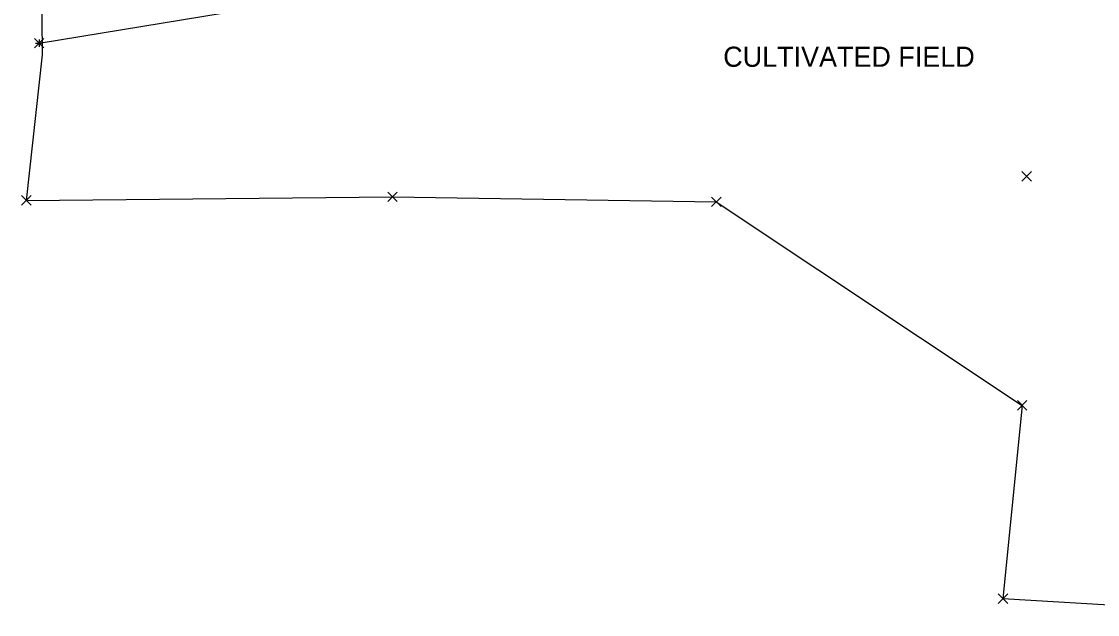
# Model space of a CAD drawing. Extents: x 211013 to 211654, y 505587 to 505872.
# Drawn here: x 211012.8 to 211162.3, y 505603.9 to 505686.3 of the extents above; entities that cross this region are included whole.
import ezdxf

# ---------------------------------------------------------------- set-up
doc = ezdxf.new("R2010")
doc.units = 0
for name, color, linetype in [('DV_X_Section_VMS_Line', 7, 'Continuous'), ('GE_X_Alignment', 7, 'Continuous'), ('RW_X_Esmt_SH', 7, 'Continuous'), ('SV_X_Terrain_Boundary', 7, 'Continuous'), ('SV_X_Text', 7, 'Continuous')]:
    doc.layers.add(name, color=color, linetype=linetype)

msp = doc.modelspace()

# ---------------------------------------------------------------- linework, layer by layer
at = {"layer": 'DV_X_Section_VMS_Line'}
for p, q in [((211014.76, 505683.32), (211015.76, 505683.32)), ((211015.26, 505683.82), (211015.26, 505682.82)), ((211015.26, 505683.32), (211015.26, 505683.32))]:
    msp.add_line(p, q, dxfattribs=at)
at = {"layer": 'GE_X_Alignment'}
msp.add_lwpolyline([(211015.26, 505683.32), (211080.5, 505694.08), (211109.4, 505697.19), (211135.16, 505699.18), (211157.57, 505696.9), (211176.08, 505692.43), (211181.06, 505676.6), (211185.07, 505653.12), (211186.49, 505625.48), (211186.51, 505603.87)], dxfattribs=at)
at = {"layer": 'RW_X_Esmt_SH'}
for p, q in [((211014.59, 505682.66), (211015.92, 505683.99)), ((211014.59, 505683.99), (211015.92, 505682.66)), ((211151.83, 505664.15), (211153.16, 505665.48)), ((211151.83, 505665.48), (211153.16, 505664.15)), ((211012.8, 505660.79), (211014.13, 505662.13)), ((211012.8, 505662.13), (211014.13, 505660.79)), ((211063.69, 505661.29), (211065.02, 505662.62)), ((211063.69, 505662.62), (211065.02, 505661.29)), ((211108.69, 505660.59), (211110.02, 505661.93)), ((211108.69, 505661.93), (211110.02, 505660.59)), ((211151.2, 505632.29), (211152.53, 505633.62)), ((211151.2, 505633.62), (211152.53, 505632.29)), ((211148.51, 505605.41), (211149.85, 505606.75)), ((211148.51, 505606.75), (211149.85, 505605.41))]:
    msp.add_line(p, q, dxfattribs=at)
at = {"layer": 'SV_X_Terrain_Boundary'}
msp.add_lwpolyline([(211258.57, 505812.76), (211238.01, 505789.67), (211208.95, 505771.3), (211161.33, 505774.75), (211112.02, 505773.7), (211055.47, 505773.4), (211013.95, 505769.7), (211014.38, 505747.97), (211015.17, 505738.62), (211015.65, 505681.68), (211013.46, 505661.46), (211064.36, 505661.96), (211109.35, 505661.26), (211151.86, 505632.96), (211149.18, 505606.08), (211186.51, 505603.87), (211206.35, 505610.45), (211218.51, 505613.39), (211247.2, 505610.15), (211268.66, 505610.6)], dxfattribs=at)

# ---------------------------------------------------------------- texts
at = {"layer": 'SV_X_Text'}
msp.add_text('CULTIVATED FIELD', height=2.8, dxfattribs=at).set_placement((211110.32, 505680.04))

doc.saveas('drawing.dxf')
